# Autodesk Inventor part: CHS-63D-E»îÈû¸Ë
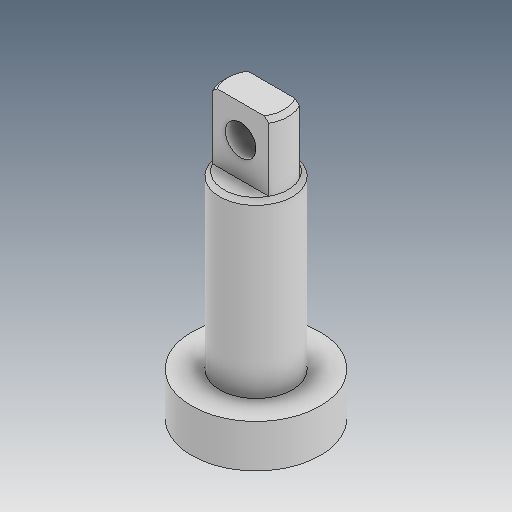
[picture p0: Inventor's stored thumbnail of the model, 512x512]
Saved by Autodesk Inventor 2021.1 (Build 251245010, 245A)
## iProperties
Created: 2019-05
Part Number: CHS-63D-E»îÈû¸Ë
Material: Ogólny
Document SubType Name: Modeling
Designer: user
Density: 1 g/cm^3
Appearance: Domyślna
Author: user
Revision Number: ÈÎºÎ
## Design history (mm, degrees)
feature "ÊäÈë1"
feature "ÊäÈë2"
node "Bryła1"
node "Bryła2"
